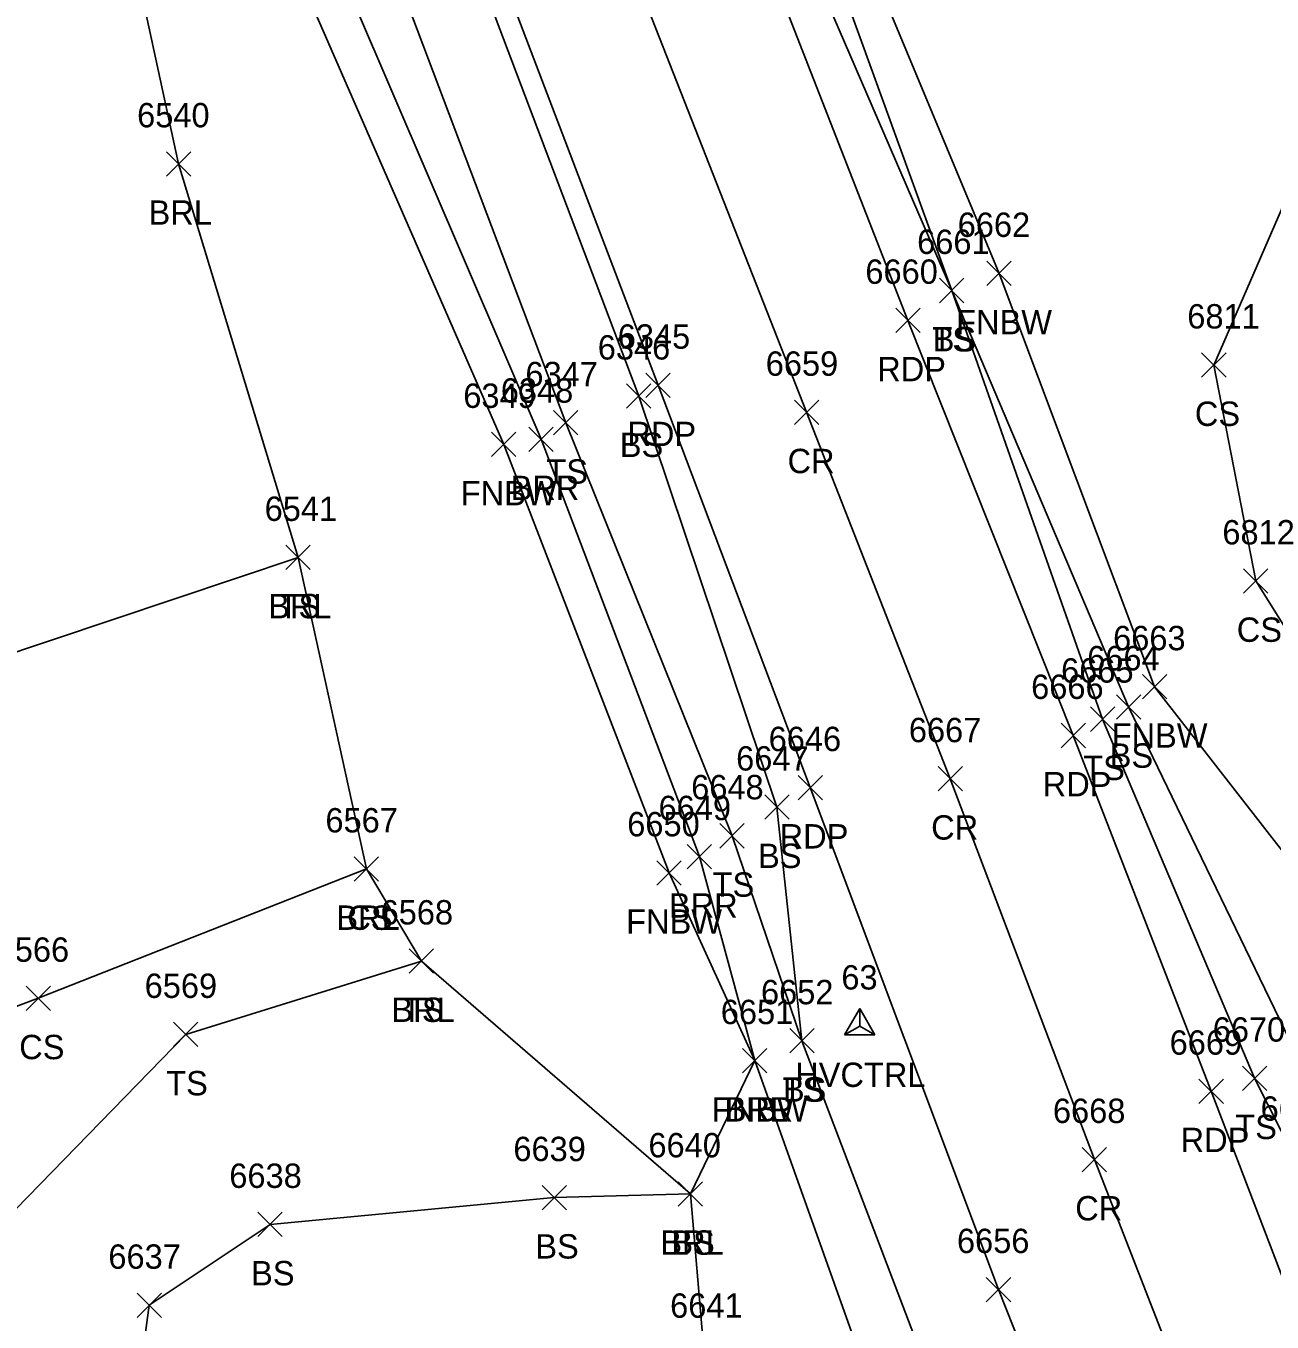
# Model space of a CAD drawing. Extents: x 1472233 to 1475777, y 540726 to 543442.
# Drawn here: x 1472552.6 to 1472654.9, y 541371.4 to 541477.9 of the extents above; entities that cross this region are included whole.
import ezdxf

# ---------------------------------------------------------------- set-up
doc = ezdxf.new("R2010")
doc.units = 0
for name, color, linetype in [('C_A', 7, 'Continuous'), ('C_I', 7, 'Continuous'), ('CPSM', 7, 'Continuous'), ('L_A', 7, 'Continuous'), ('L_I', 7, 'Continuous'), ('L_TIC', 7, 'Continuous'), ('LABL', 7, 'Continuous'), ('LELB', 7, 'Continuous'), ('LFNC', 7, 'Continuous'), ('P_A', 7, 'Continuous'), ('P_I', 7, 'Continuous'), ('P_TIC', 7, 'Continuous'), ('PET', 7, 'Continuous'), ('PRC', 7, 'Continuous')]:
    doc.layers.add(name, color=color, linetype=linetype)

msp = doc.modelspace()

# ---------------------------------------------------------------- linework, layer by layer
at = {"layer": 'CPSM'}
for p, q in [((1472619.84, 541395.02), (1472621.09, 541397.19)), ((1472622.34, 541395.02), (1472621.09, 541397.19)), ((1472621.09, 541395.74), (1472621.09, 541397.19)), ((1472619.84, 541395.02), (1472621.09, 541395.74)), ((1472621.09, 541395.74), (1472621.09, 541395.74)), ((1472621.09, 541395.74), (1472622.34, 541395.02)), ((1472619.84, 541395.02), (1472622.34, 541395.02))]:
    msp.add_line(p, q, dxfattribs=at)
at = {"layer": 'L_TIC'}
for points in [[(1472564.16, 541465.54), (1472566.16, 541467.54)], [(1472566.16, 541465.54), (1472564.16, 541467.54)], [(1472631.53, 541456.54), (1472633.53, 541458.54)], [(1472633.53, 541456.54), (1472631.53, 541458.54)], [(1472627.64, 541455.14), (1472629.64, 541457.14)], [(1472629.64, 541455.14), (1472627.64, 541457.14)], [(1472627.64, 541455.14), (1472629.64, 541457.14)], [(1472629.64, 541455.14), (1472627.64, 541457.14)], [(1472649.16, 541449.02), (1472651.16, 541451.02)], [(1472651.16, 541449.02), (1472649.16, 541451.02)], [(1472601.95, 541446.47), (1472603.95, 541448.47)], [(1472603.95, 541446.47), (1472601.95, 541448.47)], [(1472595.95, 541444.28), (1472597.95, 541446.28)], [(1472597.95, 541444.28), (1472595.95, 541446.28)], [(1472590.86, 541442.5), (1472592.86, 541444.5)], [(1472592.86, 541442.5), (1472590.86, 541444.5)], [(1472593.93, 541442.93), (1472595.93, 541444.93)], [(1472595.93, 541442.93), (1472593.93, 541444.93)], [(1472573.97, 541433.22), (1472575.97, 541435.22)], [(1472575.97, 541433.22), (1472573.97, 541435.22)], [(1472573.97, 541433.22), (1472575.97, 541435.22)], [(1472575.97, 541433.22), (1472573.97, 541435.22)], [(1472652.6, 541431.29), (1472654.6, 541433.29)], [(1472654.6, 541431.29), (1472652.6, 541433.29)], [(1472644.3, 541422.6), (1472646.3, 541424.6)], [(1472646.3, 541422.6), (1472644.3, 541424.6)], [(1472642.16, 541420.95), (1472644.16, 541422.95)], [(1472644.16, 541420.95), (1472642.16, 541422.95)], [(1472640.03, 541419.94), (1472642.03, 541421.94)], [(1472642.03, 541419.94), (1472640.03, 541421.94)], [(1472613.29, 541412.72), (1472615.29, 541414.72)], [(1472615.29, 541412.72), (1472613.29, 541414.72)], [(1472609.61, 541410.36), (1472611.61, 541412.36)], [(1472611.61, 541410.36), (1472609.61, 541412.36)], [(1472606.93, 541408.65), (1472608.93, 541410.65)], [(1472608.93, 541408.65), (1472606.93, 541410.65)], [(1472579.58, 541407.64), (1472581.58, 541409.64)], [(1472581.58, 541407.64), (1472579.58, 541409.64)], [(1472579.58, 541407.64), (1472581.58, 541409.64)], [(1472581.58, 541407.64), (1472579.58, 541409.64)], [(1472604.44, 541407.32), (1472606.44, 541409.32)], [(1472606.44, 541407.32), (1472604.44, 541409.32)], [(1472584.1, 541400.08), (1472586.1, 541402.08)], [(1472586.1, 541400.08), (1472584.1, 541402.08)], [(1472584.1, 541400.08), (1472586.1, 541402.08)], [(1472586.1, 541400.08), (1472584.1, 541402.08)], [(1472552.64, 541397.02), (1472554.64, 541399.02)], [(1472554.64, 541397.02), (1472552.64, 541399.02)], [(1472564.75, 541394.05), (1472566.75, 541396.05)], [(1472566.75, 541394.05), (1472564.75, 541396.05)], [(1472615.34, 541393.53), (1472617.34, 541395.53)], [(1472617.34, 541393.53), (1472615.34, 541395.53)], [(1472615.34, 541393.53), (1472617.34, 541395.53)], [(1472617.34, 541393.53), (1472615.34, 541395.53)], [(1472611.47, 541391.9), (1472613.47, 541393.9)], [(1472613.47, 541391.9), (1472611.47, 541393.9)], [(1472611.47, 541391.9), (1472613.47, 541393.9)], [(1472613.47, 541391.9), (1472611.47, 541393.9)], [(1472611.47, 541391.9), (1472613.47, 541393.9)], [(1472613.47, 541391.9), (1472611.47, 541393.9)], [(1472652.51, 541390.46), (1472654.51, 541392.46)], [(1472654.51, 541390.46), (1472652.51, 541392.46)], [(1472606.18, 541380.96), (1472608.18, 541382.96)], [(1472608.18, 541380.96), (1472606.18, 541382.96)], [(1472606.18, 541380.96), (1472608.18, 541382.96)], [(1472608.18, 541380.96), (1472606.18, 541382.96)], [(1472595.01, 541380.65), (1472597.01, 541382.65)], [(1472597.01, 541380.65), (1472595.01, 541382.65)], [(1472571.68, 541378.45), (1472573.68, 541380.45)], [(1472573.68, 541378.45), (1472571.68, 541380.45)], [(1472561.76, 541371.81), (1472563.76, 541373.81)], [(1472563.76, 541371.81), (1472561.76, 541373.81)]]:
    msp.add_lwpolyline(points, dxfattribs=at)
at = {"layer": 'LABL'}
for points in [[(1472524.54, 541604.06), (1472530.88, 541605.13), (1472533.72, 541596.51), (1472543.81, 541568.69), (1472561.11, 541526.99), (1472576.55, 541486.83), (1472594.93, 541443.93), (1472607.93, 541409.65), (1472612.47, 541392.9)], [(1472524.54, 541604.06), (1472528.33, 541570.22), (1472538.7, 541544.98), (1472550.2, 541522.43), (1472558.52, 541497.28), (1472565.16, 541466.54), (1472574.97, 541434.22), (1472580.58, 541408.64), (1472585.1, 541401.08), (1472607.18, 541381.96), (1472612.47, 541392.9)]]:
    msp.add_lwpolyline(points, dxfattribs=at)
at = {"layer": 'LELB'}
for points in [[(1472484.34, 541840.42), (1472508.51, 541798.7), (1472519.34, 541760.36), (1472543.64, 541727.26), (1472543.24, 541715), (1472560.46, 541670.84), (1472572.87, 541630.9), (1472574.19, 541601.93), (1472592.34, 541551.17), (1472612.27, 541501.36), (1472628.64, 541456.14), (1472641.03, 541420.94), (1472653.51, 541391.46), (1472656.79, 541384.97), (1472662.92, 541362.2), (1472669.18, 541346.61), (1472674.21, 541333.47)], [(1472448.1, 541812.75), (1472448.35, 541808.89), (1472456.83, 541789.05), (1472474.31, 541748.23), (1472493.04, 541702.8), (1472494.57, 541702.64), (1472518, 541641.77), (1472527.77, 541616.94), (1472533.94, 541611.96), (1472541.35, 541598.76), (1472552.58, 541572.19), (1472569.89, 541532.32), (1472586.68, 541490.5), (1472602.95, 541447.47), (1472614.29, 541413.72), (1472616.34, 541394.53)], [(1472540.25, 541666.6), (1472558.15, 541629.07), (1472569.04, 541603.36), (1472584.13, 541563.55), (1472589.42, 541549.68), (1472609.63, 541500.17), (1472628.64, 541456.14), (1472643.16, 541421.95), (1472658.35, 541390.54), (1472659.79, 541385.27), (1472666.4, 541363.57), (1472670.68, 541348), (1472676.96, 541338.56), (1472681.26, 541333.23)], [(1472530.88, 541605.13), (1472536.76, 541597.99), (1472547.28, 541570.04), (1472564.19, 541527.09), (1472580.43, 541489.05), (1472596.95, 541445.28), (1472610.61, 541411.36), (1472616.34, 541394.53), (1472627.95, 541364.05), (1472634.3, 541352.48), (1472639.77, 541346.17), (1472644.32, 541334.93), (1472647.68, 541327.12), (1472650.87, 541311.53), (1472653.05, 541303.09), (1472658.89, 541293.28), (1472670.29, 541260.53), (1472686.41, 541223.33)], [(1472748.86, 541515.07), (1472733.37, 541506.2), (1472712.89, 541502.15), (1472673.02, 541491.92), (1472657.9, 541467.84), (1472650.16, 541450.02), (1472653.6, 541432.29), (1472661.59, 541419.53), (1472668.41, 541419.29), (1472679.96, 541433.41), (1472687.47, 541437)], [(1472574.97, 541434.22), (1472549.65, 541425.73), (1472522.78, 541424.88), (1472494.81, 541420.51), (1472473.98, 541412.81)], [(1472485.6, 541375.74), (1472506.37, 541383.47), (1472529.58, 541388.94), (1472553.64, 541398.02), (1472580.58, 541408.64)], [(1472585.1, 541401.08), (1472565.75, 541395.05), (1472548.77, 541377.62), (1472550.05, 541347.94), (1472535.73, 541333.01), (1472510.7, 541352.61)], [(1472559.01, 541344.89), (1472562.76, 541372.81), (1472572.68, 541379.45), (1472596.01, 541381.65), (1472607.18, 541381.96), (1472608.31, 541368.79), (1472613.73, 541355.01), (1472629.56, 541348.93)]]:
    msp.add_lwpolyline(points, dxfattribs=at)
at = {"layer": 'LFNC'}
for points in [[(1472546.47, 541665.22), (1472562.01, 541628.06), (1472574.19, 541601.93), (1472596.84, 541552.46), (1472613.94, 541502.19), (1472632.53, 541457.54), (1472645.3, 541423.6), (1472667.84, 541394.65), (1472670.15, 541396.24), (1472675.13, 541398.08), (1472685.24, 541400.01)], [(1472556.2, 541526.44), (1472573.35, 541485.94), (1472591.86, 541443.5), (1472605.44, 541408.32), (1472612.47, 541392.9), (1472623.1, 541363.11)]]:
    msp.add_lwpolyline(points, dxfattribs=at)
at = {"layer": 'P_TIC'}
for points in [[(1472624.04, 541452.69), (1472626.04, 541454.69)], [(1472626.04, 541452.69), (1472624.04, 541454.69)], [(1472603.53, 541447.36), (1472605.53, 541449.36)], [(1472605.53, 541447.36), (1472603.53, 541449.36)], [(1472615.73, 541445.14), (1472617.73, 541447.14)], [(1472617.73, 541445.14), (1472615.73, 541447.14)], [(1472637.62, 541418.6), (1472639.62, 541420.6)], [(1472639.62, 541418.6), (1472637.62, 541420.6)], [(1472627.52, 541415.05), (1472629.52, 541417.05)], [(1472629.52, 541415.05), (1472627.52, 541417.05)], [(1472616.02, 541414.32), (1472618.02, 541416.32)], [(1472618.02, 541414.32), (1472616.02, 541416.32)], [(1472648.94, 541389.39), (1472650.94, 541391.39)], [(1472650.94, 541389.39), (1472648.94, 541391.39)], [(1472639.35, 541383.78), (1472641.35, 541385.78)], [(1472641.35, 541383.78), (1472639.35, 541385.78)], [(1472631.48, 541373.1), (1472633.48, 541375.1)], [(1472633.48, 541373.1), (1472631.48, 541375.1)]]:
    msp.add_lwpolyline(points, dxfattribs=at)
at = {"layer": 'PET'}
for points in [[(1472431.81, 541951), (1472434.94, 541942.83), (1472440.19, 541926.31), (1472454.88, 541886.72), (1472470.9, 541847.46), (1472487.25, 541799.16), (1472502.86, 541758.42), (1472521.3, 541713.6), (1472521.81, 541711.24), (1472540.25, 541666.6), (1472555.59, 541628.47), (1472566.44, 541602.13), (1472581.86, 541563.08), (1472587.45, 541548.93), (1472607.29, 541499.12), (1472625.04, 541453.69), (1472638.62, 541419.6), (1472649.94, 541390.39), (1472660.9, 541361.79), (1472670.65, 541335.94), (1472680.31, 541310.93), (1472684.25, 541300.56), (1472697.31, 541267.54), (1472711.09, 541230.89)], [(1472410.42, 541944.75), (1472417.04, 541924.07), (1472429.27, 541890.41), (1472437.03, 541868.87), (1472443.66, 541851.19), (1472458.48, 541813.05), (1472466.78, 541792.24), (1472482.95, 541751.29), (1472501.43, 541706.5), (1472501.82, 541705.19), (1472522.02, 541654.99), (1472538.62, 541615.01), (1472544.85, 541600.28), (1472555.29, 541573.09), (1472571.16, 541534.06), (1472588.21, 541491.28), (1472604.53, 541448.36), (1472617.02, 541415.32), (1472632.48, 541374.1), (1472640.33, 541354.3), (1472653.53, 541321.3), (1472663.39, 541294.75), (1472676.2, 541262.98), (1472690.88, 541224.88)]]:
    msp.add_lwpolyline(points, dxfattribs=at)
at = {"layer": 'PRC'}
msp.add_lwpolyline([(1472420.86, 541948.25), (1472433.46, 541909.93), (1472447.3, 541871.91), (1472463.52, 541829.07), (1472476.48, 541795.89), (1472493.07, 541754.32), (1472510.83, 541710.45), (1472511.85, 541707.67), (1472530.21, 541662.33), (1472546.22, 541622.93), (1472556.77, 541597.06), (1472571.64, 541559.78), (1472578.28, 541543.8), (1472597.24, 541495.81), (1472616.73, 541446.14), (1472628.52, 541416.05), (1472640.35, 541384.78), (1472651, 541357.43), (1472663.57, 541324.45), (1472674.03, 541297.85), (1472686.99, 541264.4), (1472700.97, 541228.15)], dxfattribs=at)

# ---------------------------------------------------------------- texts
at = {"layer": 'C_A'}
msp.add_text('HVCTRL', height=2, dxfattribs=at).set_placement((1472615.79, 541390.74))
at = {"layer": 'C_I'}
msp.add_text('63', height=2, dxfattribs=at).set_placement((1472619.58, 541398.74))
at = {"layer": 'L_A'}
for s, p in [('BRL', (1472562.7, 541461.54)), ('FNBW', (1472629, 541452.54)), ('TS', (1472627.05, 541451.14)), ('BS', (1472627.08, 541451.14)), ('CS', (1472648.6, 541445.02)), ('BS', (1472601.39, 541442.47)), ('TS', (1472595.36, 541440.28)), ('FNBW', (1472588.33, 541438.5)), ('BRR', (1472592.42, 541438.93)), ('BRL', (1472572.52, 541429.22)), ('TS', (1472573.38, 541429.22)), ('CS', (1472652.04, 541427.29)), ('FNBW', (1472641.77, 541418.6)), ('BS', (1472641.61, 541416.95)), ('TS', (1472639.44, 541415.94)), ('BS', (1472612.74, 541408.72)), ('TS', (1472609.01, 541406.36)), ('BRR', (1472605.42, 541404.65)), ('BRL', (1472578.12, 541403.64)), ('CS', (1472579.02, 541403.64)), ('FNBW', (1472601.91, 541403.32)), ('BRL', (1472582.64, 541396.08)), ('TS', (1472583.51, 541396.08)), ('CS', (1472552.08, 541393.02)), ('TS', (1472564.15, 541390.05)), ('TS', (1472614.75, 541389.53)), ('BS', (1472614.78, 541389.53)), ('FNBW', (1472608.94, 541387.9)), ('BRR', (1472609.96, 541387.9)), ('BRL', (1472610.01, 541387.9)), ('TS', (1472651.92, 541386.46)), ('BS', (1472594.45, 541376.65)), ('BRL', (1472604.72, 541376.96)), ('BS', (1472605.62, 541376.96)), ('BS', (1472571.12, 541374.45))]:
    msp.add_text(s, height=2, dxfattribs=at).set_placement(p)
at = {"layer": 'L_I'}
for s, p in [('6540', (1472561.76, 541469.54)), ('6662', (1472629.13, 541460.54)), ('6661', (1472625.8, 541459.14)), ('6661', (1472625.8, 541459.14)), ('6811', (1472647.98, 541453.02)), ('6346', (1472599.58, 541450.47)), ('6347', (1472593.64, 541448.28)), ('6348', (1472591.62, 541446.93)), ('6349', (1472588.54, 541446.5)), ('6541', (1472572.23, 541437.22)), ('6541', (1472572.23, 541437.22)), ('6812', (1472650.86, 541435.29)), ('6663', (1472641.89, 541426.6)), ('6664', (1472639.76, 541424.95)), ('6665', (1472637.62, 541423.94)), ('6647', (1472610.94, 541416.72)), ('6648', (1472607.25, 541414.36)), ('6649', (1472604.57, 541412.65)), ('6567', (1472577.22, 541411.64)), ('6567', (1472577.22, 541411.64)), ('6650', (1472602, 541411.32)), ('6568', (1472581.75, 541404.08)), ('6568', (1472581.75, 541404.08)), ('6566', (1472550.23, 541401.02)), ('6569', (1472562.38, 541398.05)), ('6652', (1472612.98, 541397.53)), ('6652', (1472612.98, 541397.53)), ('6651', (1472609.68, 541395.9)), ('6651', (1472609.68, 541395.9)), ('6651', (1472609.68, 541395.9)), ('6670', (1472650.07, 541394.46)), ('6671', (1472654, 541387.97)), ('6671', (1472654, 541387.97)), ('6640', (1472603.74, 541384.96)), ('6640', (1472603.74, 541384.96)), ('6639', (1472592.65, 541384.65)), ('6638', (1472569.33, 541382.45)), ('6637', (1472559.4, 541375.81)), ('6641', (1472605.52, 541371.79))]:
    msp.add_text(s, height=2, dxfattribs=at).set_placement(p)
at = {"layer": 'P_A'}
for s, p in [('RDP', (1472622.52, 541448.69)), ('RDP', (1472602.01, 541443.36)), ('CR', (1472615.16, 541441.14)), ('RDP', (1472636.11, 541414.6)), ('CR', (1472626.95, 541411.05)), ('RDP', (1472614.51, 541410.32)), ('RDP', (1472647.43, 541385.39)), ('CR', (1472638.78, 541379.78))]:
    msp.add_text(s, height=2, dxfattribs=at).set_placement(p)
at = {"layer": 'P_I'}
for s, p in [('6660', (1472621.55, 541456.69)), ('6345', (1472601.22, 541451.36)), ('6659', (1472613.37, 541449.14)), ('6666', (1472635.16, 541422.6)), ('6667', (1472625.12, 541419.05)), ('6646', (1472613.61, 541418.32)), ('6669', (1472646.53, 541393.39)), ('6668', (1472636.95, 541387.78)), ('6656', (1472629.07, 541377.1))]:
    msp.add_text(s, height=2, dxfattribs=at).set_placement(p)

doc.saveas('drawing.dxf')
